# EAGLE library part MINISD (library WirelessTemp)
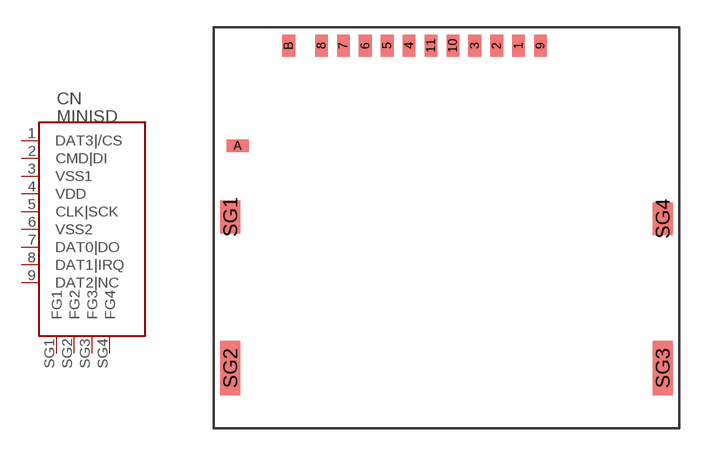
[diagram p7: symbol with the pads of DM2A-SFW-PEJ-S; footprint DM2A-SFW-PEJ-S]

Designator prefix CN

## MINISD  [DM2A-SFW-PEJ-S]
1  DAT3|/CS  in
2  CMD|DI  in
3  VSS1  pwr
4  VDD  pwr
5  CLK|SCK  in
6  VSS2  pwr
7  DAT0|DO  out
8  DAT1|IRQ  nc
9  DAT2|NC  nc
SG1  FG1  pwr
SG2  FG2  pwr
SG3  FG3  pwr
SG4  FG4  pwr

## Footprint DM2A-SFW-PEJ-S (pad centres in mm)
Mini-SD card connector Mfg. Hirose PN DM2A-SFW-PEK-S
smd 0.7 x 1.2: 1 10.8,0.6; 2 9.6,0.6; 3 8.4,0.6; 4 4.8,0.6; 5 3.6,0.6; 6 2.4,0.6; 7 1.2,0.6; 8 0,0.6; 9 12,0.6; 10 7.2,0.6; 11 6,0.6; B -1.8,0.6
smd 1.2 x 0.7: A -4.6,-4.9
smd 1.1 x 1.8: SG1 -5,-8.8; SG4 18.7,-8.9
smd 1.1 x 3: SG2 -5,-17.1; SG3 18.7,-17.1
